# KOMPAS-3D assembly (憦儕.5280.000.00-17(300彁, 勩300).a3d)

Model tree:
1. Плоскость XY
2. Плоскость ZX
3. Плоскость ZY
4. Ось X
5. Ось Y
6. Ось Z
7. Начало координат  (labels: Операция без истории:1; Операция без истории:2; Операция без истории:3; Операция без истории:4)

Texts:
  Линия-выноска #1
  Линия-выноска #2
  Линия-выноска #3
  Отклонения формы и база
  Марка координационной оси
  Марка/позиционное обозначение с линией-выноской
  Марка/позиционное обозначение на линии
  Марка/позиционное обозначение без линии-выноски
